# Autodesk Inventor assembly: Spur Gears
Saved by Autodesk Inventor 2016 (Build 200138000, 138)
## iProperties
Created: 2016-10
Part Number: Spur Gears
Document SubType Name: Assembly
Designer: Ingenieria
Categories: <?xml version="1.0" encoding="UTF-16"?> <MemberInstance><Categories><FamilyTemplate/><ParamToTemplateMap><ParamToTemplate><ParamToTemplate CategoryParameter="//
ClientObjectVersion: 1
Author: Ingenieria
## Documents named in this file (2)
- C:\Users\ingenieria\Desktop\INGENIERIA\Proyectos\2016\Enfriador_4\Planos\Montaje_satelites\Design Accelerator\Spur Gears1.iam
- C:\Users\ingenieria\Desktop\INGENIERIA\Proyectos\2016\Enfriador_4\Planos\Montaje_satelites\Design Accelerator\Spur Gear11.ipt
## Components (1 placed, 1 different names)
1. Spur Gear1:1
